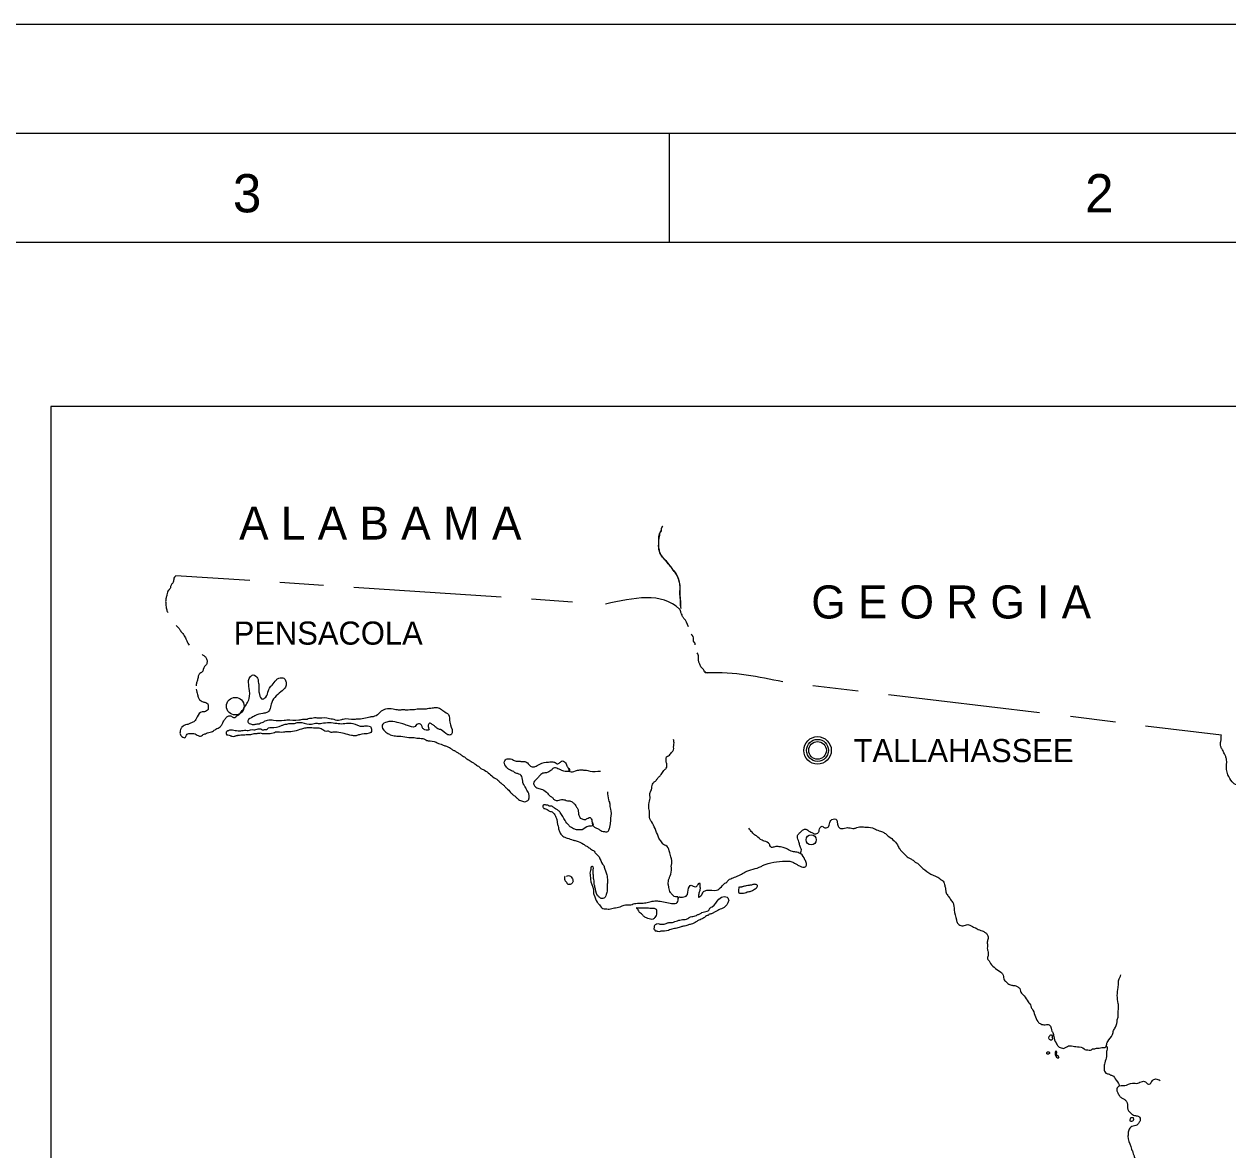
# Model space of a CAD drawing. Extents: x 464090 to 640095, y 2137521 to 2273520.
# Drawn here: x 584083 to 606122, y 2252910 to 2273520 of the extents above; entities that cross this region are included whole.
import ezdxf

# ---------------------------------------------------------------- set-up
doc = ezdxf.new("R2010")
doc.units = 0
for name, color, linetype in [('G-ANNO-NPLT', 7, 'Continuous'), ('G-ANNO-TTLB', 7, 'Continuous'), ('V-ANNO-SYMB', 7, 'Continuous')]:
    doc.layers.add(name, color=color, linetype=linetype)

msp = doc.modelspace()

# ---------------------------------------------------------------- linework, layer by layer
at = {"layer": 'G-ANNO-NPLT'}
msp.add_lwpolyline([(464090, 2273520), (640089, 2273520), (640089, 2137521), (464090, 2137521)], close=True, dxfattribs=at)
at = {"layer": 'G-ANNO-TTLB'}
msp.add_line((595890, 2271520), (595890, 2269520), dxfattribs=at)
for points in [[(466090, 2139521), (638089, 2139521), (638089, 2271520), (466090, 2271520)], [(636089, 2269520), (471090, 2269520), (471090, 2141521), (636089, 2141521)]]:
    msp.add_lwpolyline(points, close=True, dxfattribs=at)
at = {"layer": 'V-ANNO-SYMB'}
for p, q in [((624088, 2266520), (584575, 2266520)), ((584575, 2266520), (584575, 2230868)), ((588213, 2263332), (586864, 2263422)), ((589567, 2263241), (588766, 2263296)), ((592820, 2263029), (590117, 2263206)), ((594123, 2262937), (593370, 2262992)), ((599352, 2261307), (598523, 2261405)), ((602675, 2260912), (599910, 2261239)), ((604061, 2260740), (603238, 2260844)), ((606004, 2260506), (604614, 2260669)), ((598378, 2258223), (598375, 2258226))]:
    msp.add_line(p, q, dxfattribs=at)
for centre, radius in [((587949, 2261034), 161), ((598609, 2260224), 252), ((598609, 2260224), 201), ((598609, 2260224), 161), ((598493, 2258586), 93.6)]:
    msp.add_circle(centre, radius, dxfattribs=at)
msp.add_arc((596630, 2261756), 122, 213.1829, 248.6294, dxfattribs=at)
for points in [[(596113, 2262824), (596102, 2262878), (596102, 2262974), (596094, 2263083), (596094, 2263209), (596075, 2263333), (596039, 2263423), (595987, 2263500), (595914, 2263598), (595816, 2263715), (595739, 2263811), (595701, 2263933), (595704, 2264080), (595717, 2264190), (595750, 2264247), (595750, 2264277), (595777, 2264331)], [(596114, 2262820), (596107, 2262841), (596107, 2262939), (596092, 2263039), (596092, 2263227), (596078, 2263317), (596046, 2263410), (595988, 2263504), (595966, 2263525), (595923, 2263590), (595873, 2263641), (595808, 2263727), (595761, 2263777), (595718, 2263867), (595704, 2263947), (595704, 2264055), (595711, 2264119), (595718, 2264145), (595725, 2264209), (595747, 2264245), (595754, 2264289), (595776, 2264332)], [(586864, 2263422), (586838, 2263397), (586822, 2263350), (586807, 2263293), (586773, 2263248), (586761, 2263202), (586746, 2263173), (586730, 2263157), (586698, 2263074), (586683, 2263015), (586675, 2262952), (586681, 2262874), (586694, 2262797), (586702, 2262769), (586712, 2262750)], [(596246, 2262489), (596164, 2262641), (596148, 2262660), (596137, 2262677), (596131, 2262704), (596109, 2262748), (596085, 2262808), (596083, 2262810), (594726, 2262903)], [(586868, 2262509), (586915, 2262464), (586944, 2262418), (586988, 2262363), (587039, 2262282), (587060, 2262231), (587106, 2262150)], [(596366, 2262156), (596363, 2262192), (596338, 2262225), (596341, 2262260), (596298, 2262353)], [(587341, 2261982), (587381, 2261954), (587418, 2261911), (587434, 2261856), (587420, 2261797), (587389, 2261763), (587334, 2261653), (587300, 2261633), (587273, 2261580), (587255, 2261507), (587237, 2261448), (587235, 2261407)], [(597971, 2261478), (596589, 2261642), (596559, 2261645), (596529, 2261691), (596485, 2261740), (596464, 2261770), (596455, 2261800), (596434, 2261849), (596431, 2261912), (596423, 2261972), (596406, 2262010)], [(587233, 2261344), (587244, 2261293), (587258, 2261250), (587265, 2261214), (587287, 2261164), (587308, 2261142), (587344, 2261121), (587409, 2261099), (587445, 2261077), (587452, 2261027), (587452, 2260973), (587424, 2260951), (587388, 2260930), (587344, 2260930), (587254, 2260836), (587226, 2260789), (587175, 2260739), (587118, 2260717), (587096, 2260703), (587060, 2260696), (586974, 2260649), (586945, 2260606), (586938, 2260555), (586938, 2260527), (586988, 2260469), (587024, 2260455), (587067, 2260519), (587139, 2260534), (587168, 2260534), (587218, 2260527), (587254, 2260505), (587312, 2260487), (587348, 2260501), (587377, 2260523), (587406, 2260530), (587442, 2260545), (587535, 2260573), (587593, 2260613), (587672, 2260656), (587708, 2260707), (587730, 2260750), (587766, 2260800), (587809, 2260847), (587859, 2260854), (587895, 2260840), (587917, 2260825), (587960, 2260840), (587982, 2260861), (588003, 2260869), (588046, 2260912), (588162, 2261081), (588205, 2261175), (588205, 2261358), (588194, 2261502), (588201, 2261542), (588230, 2261578), (588244, 2261592), (588280, 2261607), (588324, 2261585), (588370, 2261499), (588370, 2261477), (588378, 2261434), (588378, 2261344), (588392, 2261250), (588450, 2261164), (588471, 2261171), (588507, 2261200), (588558, 2261319), (588601, 2261398), (588622, 2261419), (588702, 2261517), (588745, 2261545), (588795, 2261553), (588838, 2261545), (588874, 2261488), (588882, 2261459), (588867, 2261383), (588784, 2261297), (588604, 2261070), (588576, 2260962), (588554, 2260930), (588496, 2260908), (588453, 2260901), (588309, 2260858), (588273, 2260836), (588180, 2260768), (588187, 2260732), (588230, 2260710), (588288, 2260696), (588316, 2260703), (588388, 2260710)], [(608656, 2260192), (608541, 2260213), (608570, 2260249), (608592, 2260285), (608606, 2260336), (608642, 2260372), (608728, 2260343), (608764, 2260383), (608772, 2260426), (608746, 2260483), (608718, 2260498), (608703, 2260527), (608674, 2260548), (608674, 2260577), (608667, 2260642), (608667, 2260707), (608682, 2260768), (608703, 2260818), (608718, 2260897), (608700, 2260948), (608671, 2260977), (608606, 2260969), (608577, 2260962), (608534, 2260962), (608484, 2261013), (608469, 2261034), (608440, 2261049), (608260, 2261002), (608203, 2261038), (608170, 2261077), (608113, 2261128), (608062, 2261131), (607933, 2261103), (607731, 2261160), (607710, 2261182), (607695, 2261211), (607656, 2261247), (607591, 2261247), (607562, 2261239), (607461, 2261239), (607411, 2261261), (607368, 2261326), (607353, 2261355), (607332, 2261376), (607281, 2261383), (607238, 2261398), (607191, 2261427), (607162, 2261448), (607134, 2261455), (607090, 2261455), (607069, 2261445), (607040, 2261445), (607004, 2261423), (606968, 2261394), (606910, 2261373), (606860, 2261373), (606831, 2261351), (606810, 2261247), (606795, 2261203), (606734, 2261103), (606698, 2261020), (606691, 2260955), (606691, 2260926), (606712, 2260782), (606795, 2260483), (606795, 2260455), (606802, 2260419), (606802, 2260329), (606795, 2260264), (606781, 2260228), (606777, 2260199), (606777, 2260177), (606770, 2260134), (606777, 2260069), (606777, 2259864), (606763, 2259771), (606745, 2259717), (606694, 2259623), (606680, 2259609), (606586, 2259573), (606543, 2259594), (606489, 2259630), (606468, 2259630), (606432, 2259619), (606396, 2259598), (606352, 2259591), (606331, 2259583), (606309, 2259583), (606280, 2259591), (606201, 2259648), (606122, 2259778)], [(588388, 2260710), (588417, 2260728), (588460, 2260743), (588482, 2260757), (588518, 2260771), (588604, 2260786), (588648, 2260779), (588846, 2260775), (588896, 2260782), (589112, 2260782), (589206, 2260797), (589263, 2260797), (589306, 2260815), (589350, 2260815), (589400, 2260829), (589443, 2260822), (589627, 2260822), (589677, 2260807), (589728, 2260800), (589778, 2260786), (589900, 2260789), (589922, 2260797), (590131, 2260797), (590203, 2260804), (590239, 2260804), (590365, 2260829), (590415, 2260836), (590437, 2260843), (590458, 2260843), (590552, 2260879), (590574, 2260894), (590602, 2260926), (590653, 2260962), (590703, 2260984), (590840, 2260984), (590934, 2260969), (590984, 2260969), (591013, 2260973), (591078, 2260966), (591114, 2260966), (591171, 2260973), (591207, 2260973), (591301, 2260987), (591448, 2260987), (591492, 2260998), (591528, 2260998), (591578, 2261005), (591664, 2261005), (591708, 2260984), (591765, 2260941), (591852, 2260883), (591877, 2260739), (591920, 2260563), (591898, 2260512), (591841, 2260512), (591704, 2260606), (591675, 2260613), (591610, 2260656), (591596, 2260671), (591556, 2260699), (591506, 2260721), (591484, 2260699), (591484, 2260645), (591495, 2260602), (591466, 2260595), (591420, 2260602), (591376, 2260638), (591369, 2260660), (591340, 2260703), (591268, 2260696), (591240, 2260660), (591103, 2260681), (591052, 2260696), (591016, 2260710), (590916, 2260732), (590869, 2260746), (590725, 2260743), (590638, 2260685), (590692, 2260570), (590757, 2260527), (590786, 2260512), (590836, 2260498), (590930, 2260483), (590980, 2260483), (591124, 2260462), (591196, 2260462), (591301, 2260447), (591351, 2260444), (591416, 2260429), (591459, 2260408), (591481, 2260401)], [(587812, 2260588), (587809, 2260584), (587791, 2260573), (587784, 2260555), (587784, 2260530), (587791, 2260512), (587816, 2260509), (587856, 2260494), (587874, 2260491), (587892, 2260483), (587938, 2260483), (587956, 2260491), (587992, 2260498)], [(587812, 2260588), (587830, 2260591), (587848, 2260599), (587866, 2260602), (587899, 2260599)], [(587899, 2260599), (588000, 2260584), (588050, 2260584), (588093, 2260591), (588144, 2260595), (588187, 2260588), (588230, 2260602), (588288, 2260602), (588370, 2260617), (588421, 2260617), (588442, 2260602), (588471, 2260602), (588500, 2260609), (588522, 2260609), (588558, 2260635), (588608, 2260642), (588795, 2260678), (588846, 2260699), (588874, 2260707), (588896, 2260707), (588932, 2260717), (589018, 2260717), (589083, 2260732), (589170, 2260732), (589342, 2260703), (589447, 2260721), (589490, 2260714), (589533, 2260721), (589807, 2260721), (589864, 2260714), (590102, 2260717), (590278, 2260667), (590322, 2260674), (590372, 2260674), (590422, 2260660), (590444, 2260595), (590430, 2260552), (590401, 2260537), (590221, 2260512), (590163, 2260491), (590113, 2260491), (590077, 2260498), (589814, 2260555), (589735, 2260555), (589677, 2260563), (589656, 2260577), (589612, 2260573), (589569, 2260588), (589540, 2260609), (589468, 2260631), (589382, 2260631), (589324, 2260638), (589281, 2260638), (589198, 2260624), (588932, 2260563), (588867, 2260563), (588831, 2260555), (588687, 2260555), (588644, 2260537), (588586, 2260530), (588450, 2260530), (588406, 2260537), (588342, 2260530), (588313, 2260530), (588226, 2260512), (588172, 2260512), (588122, 2260505), (588079, 2260505), (588028, 2260498), (587992, 2260498)], [(591481, 2260401), (591625, 2260372), (591668, 2260350), (591718, 2260336), (591772, 2260314), (591801, 2260307), (591852, 2260285), (591888, 2260264), (591938, 2260228), (591960, 2260221), (592003, 2260192), (592032, 2260177), (592082, 2260141), (592143, 2260105), (592172, 2260084), (592186, 2260069), (592230, 2260048), (592266, 2260019), (592309, 2259997), (592366, 2259954), (592402, 2259933), (592424, 2259911), (592514, 2259861), (592687, 2259724), (592737, 2259695), (592766, 2259673), (592780, 2259652), (592809, 2259630), (592824, 2259616), (592870, 2259580), (592906, 2259537), (592935, 2259515), (593007, 2259436), (593050, 2259400), (593072, 2259385), (593108, 2259349), (593169, 2259306), (593205, 2259292), (593248, 2259285), (593292, 2259299), (593313, 2259313), (593328, 2259371), (593328, 2259407), (593310, 2259457), (593288, 2259497), (593274, 2259519), (593259, 2259555), (593230, 2259598), (593216, 2259634), (593194, 2259749), (593119, 2259799), (593061, 2259821), (593047, 2259835), (593004, 2259850), (592975, 2259871), (592953, 2259879), (592917, 2259915), (592874, 2260008), (592896, 2260051), (592924, 2260069), (592960, 2260069), (593011, 2260062), (593040, 2260048), (593112, 2260026), (593162, 2260026), (593191, 2260019), (593248, 2260019), (593284, 2260005), (593335, 2259954), (593382, 2259925), (593425, 2259925), (593490, 2259954), (593641, 2260008), (593662, 2260008), (593706, 2260015), (593749, 2260015), (593806, 2260001), (593842, 2259979), (593893, 2260001), (593936, 2260033), (593979, 2260012), (594022, 2259943), (594030, 2259922), (594044, 2259907)], [(596060, 2257506), (596053, 2257542), (596010, 2257542), (595930, 2257607), (595916, 2257621), (595887, 2257715), (595876, 2257773), (595891, 2257877), (595912, 2257927), (595934, 2258064), (595934, 2258125), (595941, 2258147), (595941, 2258197), (595930, 2258255), (595902, 2258349), (595894, 2258385), (595830, 2258482), (595786, 2258503), (595765, 2258532), (595743, 2258568), (595729, 2258583), (595704, 2258619), (595689, 2258655), (595567, 2258921), (595549, 2258950), (595534, 2259054), (595534, 2259097), (595527, 2259133), (595527, 2259270), (595542, 2259375), (595538, 2259403), (595552, 2259468), (595567, 2259504), (595588, 2259609), (595610, 2259637), (595653, 2259673), (595668, 2259695), (595704, 2259738), (595747, 2259781), (595797, 2259857), (595840, 2259900), (595848, 2259979), (595840, 2260008), (595837, 2260059), (595844, 2260105), (595880, 2260127), (595938, 2260185), (595974, 2260235), (595974, 2260285), (595981, 2260339), (595981, 2260383), (595974, 2260426)], [(606122, 2259778), (606097, 2259875), (606097, 2260055), (606082, 2260113), (606061, 2260163), (606039, 2260199), (606032, 2260217), (606014, 2260246), (605992, 2260296), (605992, 2260390), (606000, 2260440), (606000, 2260476), (606003, 2260505)], [(594044, 2259907), (594069, 2259850), (594019, 2259835), (593965, 2259843), (593929, 2259857), (593907, 2259871), (593878, 2259879), (593835, 2259900), (593792, 2259907), (593742, 2259871), (593727, 2259857), (593691, 2259832), (593662, 2259817), (593598, 2259810), (593562, 2259796), (593526, 2259767), (593490, 2259724), (593461, 2259695), (593410, 2259619), (593425, 2259576), (593486, 2259533), (593572, 2259511), (593666, 2259439), (593716, 2259389), (593760, 2259353), (593796, 2259317), (593853, 2259310), (593943, 2259324), (593986, 2259317), (594030, 2259303), (594073, 2259299), (594130, 2259270), (594145, 2259256), (594166, 2259241), (594181, 2259209), (594217, 2259159), (594235, 2259058), (594249, 2259015), (594264, 2258986), (594300, 2258971), (594357, 2258957), (594408, 2258986), (594444, 2258993), (594480, 2258928)], [(594044, 2259907), (594076, 2259835), (594177, 2259850), (594256, 2259868), (594314, 2259868), (594336, 2259861), (594357, 2259861), (594444, 2259846), (594638, 2259846)], [(594480, 2258928), (594494, 2258856), (594537, 2258813), (594591, 2258791), (594642, 2258755), (594685, 2258741), (594728, 2258734), (594771, 2258741), (594800, 2258799), (594814, 2258860), (594822, 2258925), (594822, 2258953), (594825, 2258982), (594825, 2259151), (594811, 2259195), (594811, 2259238), (594804, 2259274), (594789, 2259317), (594771, 2259468)], [(594480, 2258928), (594494, 2258849), (594422, 2258835), (594300, 2258773), (594199, 2258773), (594163, 2258781), (594120, 2258802), (594069, 2258838), (594055, 2258853), (593986, 2258939), (593900, 2259087), (593857, 2259130), (593835, 2259144), (593792, 2259166), (593742, 2259202), (593695, 2259205), (593673, 2259220), (593652, 2259220), (593601, 2259227), (593580, 2259205), (593601, 2259162), (593626, 2259155), (593662, 2259141), (593691, 2259119), (593749, 2259097), (593799, 2259047), (593814, 2259018), (593835, 2258961), (593842, 2258932), (593850, 2258867), (593860, 2258838), (593868, 2258788), (593889, 2258727), (593911, 2258691), (593947, 2258655), (594026, 2258619), (594134, 2258583), (594188, 2258568), (594325, 2258507), (594368, 2258478), (594397, 2258464), (594454, 2258421), (594490, 2258399), (594519, 2258377), (594541, 2258349), (594588, 2258302), (594609, 2258273), (594674, 2258143), (594696, 2258115), (594703, 2258086), (594750, 2257949), (594764, 2257837), (594764, 2257794), (594757, 2257758), (594757, 2257665), (594742, 2257585), (594721, 2257539), (594663, 2257510), (594613, 2257539), (594577, 2257575), (594534, 2257722), (594519, 2257787), (594519, 2257837), (594508, 2257881), (594508, 2257917), (594501, 2257960), (594501, 2258010), (594487, 2258100), (594465, 2258093), (594458, 2258046), (594444, 2258003), (594444, 2257953), (594451, 2257895), (594451, 2257866), (594505, 2257668), (594505, 2257632), (594519, 2257575), (594577, 2257445), (594616, 2257395), (594681, 2257330), (594732, 2257323), (594818, 2257323), (594868, 2257337), (594912, 2257344), (595020, 2257373), (595048, 2257384), (595142, 2257398), (595192, 2257398), (595236, 2257413), (595336, 2257427), (595419, 2257427)], [(598378, 2258223), (598303, 2258331), (598274, 2258345), (598231, 2258359), (598152, 2258374), (598058, 2258417), (598036, 2258431), (598000, 2258439), (597957, 2258453), (597907, 2258460), (597828, 2258460), (597766, 2258449), (597738, 2258485), (597730, 2258507), (597630, 2258565), (597594, 2258579), (597493, 2258658), (597457, 2258680), (597424, 2258709), (597396, 2258741), (597352, 2258799)], [(598296, 2258341), (598310, 2258381), (598310, 2258424), (598288, 2258467), (598274, 2258529), (598245, 2258622), (598245, 2258665), (598281, 2258716), (598296, 2258730), (598346, 2258770), (598396, 2258784), (598432, 2258763), (598447, 2258748), (598526, 2258712), (598548, 2258698), (598576, 2258698), (598612, 2258712), (598641, 2258763), (598656, 2258813), (598670, 2258827), (598692, 2258835), (598720, 2258820), (598764, 2258806), (598807, 2258824), (598821, 2258853), (598836, 2258903), (598850, 2258939), (598944, 2258968), (598987, 2258838), (599030, 2258795), (599131, 2258809), (599178, 2258809), (599278, 2258795), (599329, 2258813), (599422, 2258827), (599473, 2258820), (599502, 2258820), (599653, 2258791), (599689, 2258770), (599782, 2258741), (599836, 2258712), (599865, 2258691), (599880, 2258676), (599916, 2258647), (600088, 2258467), (600106, 2258431), (600121, 2258410), (600157, 2258367), (600315, 2258237), (600344, 2258223), (600398, 2258179), (600448, 2258151), (600470, 2258129), (600769, 2257920), (600848, 2257877), (600862, 2257863), (600898, 2257841), (600920, 2257812), (600934, 2257769), (600949, 2257708), (600956, 2257650), (600981, 2257585), (601024, 2257528), (601046, 2257492), (601089, 2257434), (601111, 2257305), (601150, 2257121), (601172, 2257063), (601230, 2257020), (601273, 2257013), (601359, 2257035), (601395, 2257027), (601492, 2256977), (601514, 2256970), (601550, 2256948), (601644, 2256912), (601687, 2256883), (601723, 2256840), (601730, 2256783), (601716, 2256711), (601719, 2256675), (601719, 2256581), (601726, 2256556), (601726, 2256448), (601719, 2256426), (601748, 2256369), (601777, 2256325), (601867, 2256232), (601975, 2256160)], [(596060, 2257506), (596082, 2257542), (596110, 2257535), (596161, 2257542), (596204, 2257557), (596226, 2257589), (596262, 2257733), (596298, 2257755), (596348, 2257733), (596391, 2257733), (596434, 2257787), (596449, 2257801), (596456, 2257751), (596456, 2257675), (596438, 2257611), (596431, 2257575), (596431, 2257539), (596488, 2257582), (596524, 2257639), (596582, 2257665), (596762, 2257665), (596805, 2257686), (596892, 2257773), (596913, 2257791), (596949, 2257812), (596964, 2257834), (597043, 2257884), (597136, 2257920), (597194, 2257945), (597280, 2257996), (597576, 2258100), (597604, 2258115), (598022, 2258197), (598080, 2258197), (598155, 2258176), (598213, 2258147), (598234, 2258133), (598292, 2258104), (598342, 2258089), (598393, 2258100), (598407, 2258151), (598378, 2258223)], [(593990, 2257924), (593979, 2257906), (593976, 2257884), (593983, 2257848), (594001, 2257827), (594022, 2257791), (594040, 2257776), (594073, 2257773)], [(594012, 2257924), (594084, 2257924), (594098, 2257909), (594120, 2257873), (594130, 2257816), (594116, 2257794), (594094, 2257773), (594073, 2257773)], [(597169, 2257726), (597162, 2257675), (597162, 2257632), (597183, 2257611), (597226, 2257611), (597284, 2257618), (597320, 2257632), (597360, 2257639), (597417, 2257661), (597453, 2257683), (597504, 2257729), (597507, 2257751), (597450, 2257773)], [(597169, 2257722), (597198, 2257729), (597223, 2257729), (597241, 2257733), (597262, 2257740), (597288, 2257744), (597334, 2257758), (597356, 2257758), (597374, 2257762), (597399, 2257762), (597417, 2257769), (597450, 2257773)], [(595419, 2257427), (595513, 2257445), (595563, 2257459), (595606, 2257467), (595700, 2257467), (595938, 2257423), (595974, 2257420), (596024, 2257427), (596053, 2257456), (596060, 2257506)], [(595714, 2257045), (595801, 2257045), (595837, 2257053), (595887, 2257074), (595938, 2257074), (595974, 2257081), (596067, 2257114), (596161, 2257128), (596254, 2257157), (596269, 2257171), (596348, 2257189), (596391, 2257204), (596420, 2257218), (596442, 2257225), (596492, 2257254), (596542, 2257269), (596622, 2257305), (596629, 2257323), (596679, 2257359), (596802, 2257503), (596902, 2257549), (596953, 2257535), (596982, 2257477), (596974, 2257449), (596949, 2257395), (596899, 2257351), (596712, 2257258), (596668, 2257233), (596618, 2257218), (596604, 2257204), (596575, 2257197), (596539, 2257168), (596481, 2257132), (596438, 2257117), (596388, 2257085), (596294, 2257042), (596233, 2257027), (596197, 2257013), (596154, 2257006), (596096, 2256988), (596010, 2256966), (595966, 2256959), (595880, 2256930), (595736, 2256912)], [(595293, 2257348), (595329, 2257341), (595516, 2257341), (595567, 2257333), (595603, 2257337), (595653, 2257315), (595660, 2257247), (595653, 2257204), (595632, 2257168), (595599, 2257132), (595552, 2257132), (595502, 2257146), (595459, 2257168), (595416, 2257197), (595401, 2257218), (595365, 2257247)], [(595293, 2257348), (595304, 2257326), (595322, 2257308), (595344, 2257265), (595365, 2257247)], [(595714, 2257045), (595668, 2257045), (595646, 2257038), (595628, 2257027), (595621, 2257006), (595617, 2256977), (595610, 2256955), (595628, 2256941), (595635, 2256923), (595664, 2256919), (595682, 2256912), (595736, 2256912)], [(601975, 2256160), (601989, 2256138), (602004, 2256124), (602011, 2256088), (602040, 2256005), (602054, 2255991), (602108, 2255947), (602144, 2255933), (602202, 2255919), (602238, 2255915), (602288, 2255886), (602310, 2255865), (602324, 2255818), (602367, 2255753), (602389, 2255731), (602464, 2255623), (602515, 2255544), (602522, 2255515), (602536, 2255494), (602641, 2255260), (602655, 2255245), (602713, 2255209), (602749, 2255202), (602850, 2255199), (602886, 2255137), (602900, 2255087), (602918, 2255058), (602932, 2254986), (602976, 2254871), (602997, 2254835), (603033, 2254792), (603069, 2254777), (603112, 2254770), (603206, 2254813), (603260, 2254813), (603368, 2254799), (603490, 2254763), (603505, 2254749), (603534, 2254745), (603627, 2254745), (603642, 2254759), (603670, 2254759), (603728, 2254774), (603764, 2254774), (603814, 2254788)], [(603814, 2254788), (603886, 2254795), (603908, 2254864), (603922, 2254893), (604009, 2255022), (604030, 2255098), (604045, 2255127), (604095, 2255256), (604095, 2255278), (604110, 2255339), (604113, 2255368), (604113, 2255454), (604120, 2255505), (604120, 2255555), (604113, 2255591), (604110, 2255883), (604117, 2255926), (604117, 2255962), (604131, 2256045), (604146, 2256066), (604160, 2256117)], [(602850, 2254936), (602850, 2254986), (602893, 2255015), (602907, 2254972)], [(602850, 2254936), (602868, 2254925), (602889, 2254925), (602907, 2254929), (602914, 2254947), (602907, 2254972)], [(602860, 2254695), (602853, 2254677), (602835, 2254666), (602817, 2254662), (602806, 2254680), (602810, 2254702)], [(602810, 2254702), (602832, 2254709), (602860, 2254695)], [(602976, 2254723), (602961, 2254695), (602961, 2254651), (602983, 2254608), (603026, 2254594)], [(602976, 2254723), (602983, 2254705), (602986, 2254687), (602979, 2254651), (602997, 2254644), (603026, 2254594)], [(603897, 2254803), (603901, 2254803), (603904, 2254731), (603897, 2254695), (603897, 2254623), (603868, 2254504), (603854, 2254417), (603876, 2254331), (603904, 2254309), (603958, 2254295), (603980, 2254281), (604002, 2254273), (604074, 2254187)], [(604074, 2254187), (604124, 2254079), (604095, 2254050), (604088, 2254003), (604106, 2253953), (604142, 2253895), (604185, 2253859), (604236, 2253831), (604250, 2253816), (604279, 2253773), (604286, 2253715), (604286, 2253679), (604300, 2253629), (604326, 2253600), (604376, 2253557), (604412, 2253543), (604477, 2253528), (604506, 2253507), (604513, 2253445), (604498, 2253417), (604484, 2253395), (604455, 2253366), (604362, 2253337), (604326, 2253309), (604297, 2253233), (604297, 2253204), (604290, 2253161), (604344, 2252974), (604358, 2252923), (604372, 2252891), (604387, 2252841), (604408, 2252790), (604419, 2252661), (604419, 2252603), (604412, 2252549), (604412, 2252499), (604405, 2252477), (604405, 2252441), (604398, 2252405), (604398, 2252376), (604387, 2252049), (604380, 2251998), (604358, 2251962), (604279, 2251865), (604272, 2251829), (604264, 2251807), (604261, 2251631), (604218, 2251537), (604210, 2251494), (604167, 2251397), (604117, 2251246), (604095, 2251203), (604081, 2251181), (604070, 2251149), (603991, 2251033), (603976, 2251005), (603948, 2250961), (603919, 2250879), (603897, 2250843), (603861, 2250742), (603847, 2250691), (603818, 2250652), (603804, 2250623), (603804, 2250565), (603814, 2250537), (603822, 2250508), (603822, 2250472), (603829, 2250414), (603829, 2250378), (603800, 2250223), (603800, 2250173), (603793, 2250130), (603796, 2250033), (603789, 2249989), (603789, 2249953), (603782, 2249896), (603782, 2249867), (603742, 2249575), (603692, 2249435), (603642, 2249349), (603627, 2249298), (603627, 2249219), (603656, 2249151), (603670, 2249136), (603703, 2249064), (603724, 2249028), (603818, 2249050), (603868, 2249039), (603897, 2248956), (603912, 2248935), (603933, 2248877)], [(604128, 2254079), (604138, 2254083), (604196, 2254090), (604232, 2254090), (604372, 2254133), (604473, 2254133), (604509, 2254151), (604560, 2254165), (604596, 2254165), (604668, 2254115), (604696, 2254122), (604740, 2254180), (604797, 2254209), (604840, 2254201), (604884, 2254180)], [(604394, 2253496), (604347, 2253496), (604333, 2253481), (604329, 2253463), (604329, 2253445)], [(604329, 2253445), (604365, 2253438), (604394, 2253453), (604394, 2253496)]]:
    msp.add_spline(points, degree=3, dxfattribs=at)

# ---------------------------------------------------------------- texts
at = {"layer": 'G-ANNO-TTLB'}
for s, p in [('3', (587906, 2270074)), ('2', (603507, 2270074))]:
    msp.add_text(s, height=700, dxfattribs=at).set_placement(p)
at = {"layer": 'V-ANNO-SYMB'}
for s, height, p in [('A L A B A M A', 604.8, (588020, 2264083)), ('G E O R G I A', 604.8, (598494, 2262639)), ('PENSACOLA', 423.4, (587920, 2262160)), ('TALLAHASSEE', 423.36, (599268, 2260009))]:
    msp.add_text(s, height=height, rotation=0, dxfattribs=at).set_placement(p)

doc.saveas('drawing.dxf')
